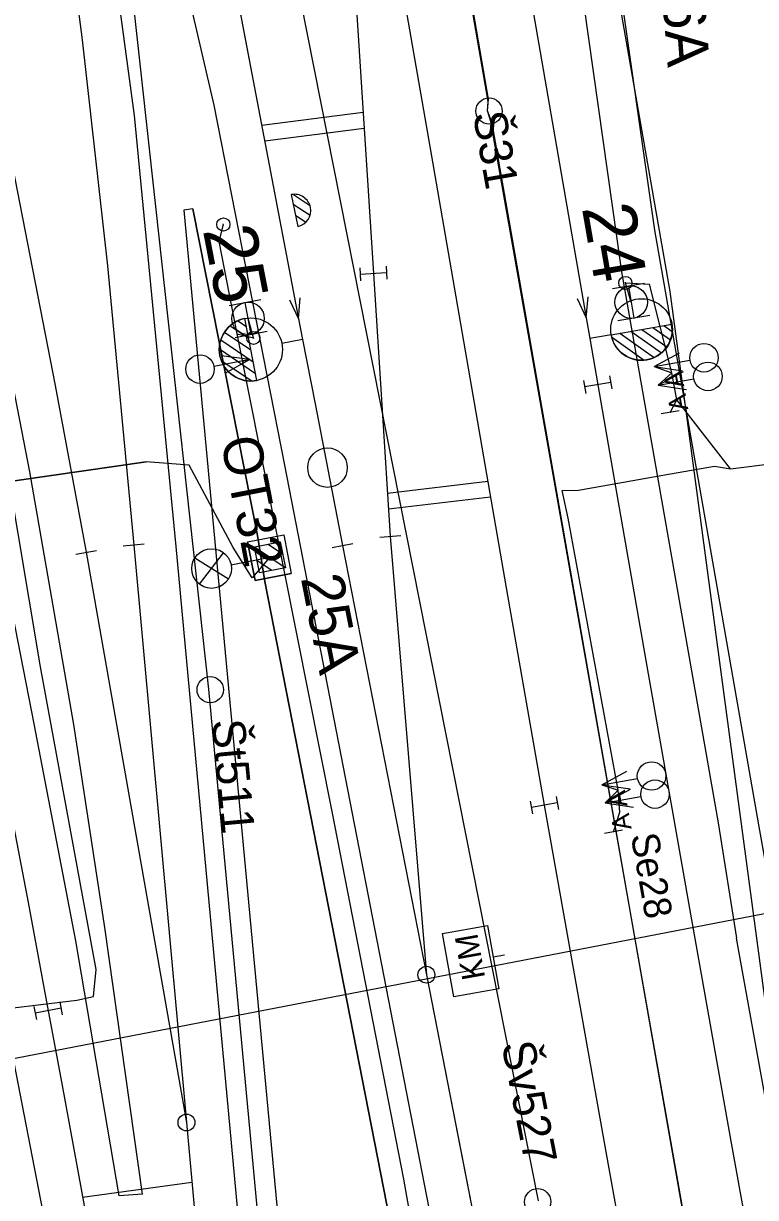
# Model space of a CAD drawing. Extents: x -545736 to -544888, y -1122892 to -1119128.
# Drawn here: x -545134.88 to -545107.08, y -1122251.17 to -1122206.55 of the extents above; entities that cross this region are included whole.
import ezdxf

# ---------------------------------------------------------------- set-up
doc = ezdxf.new("R2010")
doc.units = 0
for name, color, linetype in [('osvětlené plochy-hodnota-obrys', 7, 'Continuous'), ('Vrstva 1 - Koleje', 7, 'Continuous'), ('Vrstva 11 - Trakce', 7, 'Continuous'), ('Vrstva 12 - Trakce zaklady', 7, 'Continuous'), ('Vrstva 19 - Staniceni', 7, 'Continuous'), ('Vrstva 2 - Vyhybky', 7, 'Continuous'), ('Vrstva 25', 7, 'Continuous'), ('Vrstva 26', 7, 'Continuous'), ('Vrstva 27', 7, 'Continuous'), ('Vrstva 28 - zabzar', 7, 'Continuous'), ('Vrstva 3 - Lisy - Pocitaci body', 7, 'Continuous'), ('Vrstva 35', 7, 'Continuous'), ('Vrstva 4 - Teren - stezky - prechody - plochy', 7, 'Continuous'), ('Vrstva 43', 7, 'Continuous'), ('Vrstva 44', 7, 'Continuous'), ('Vrstva 6 - Navesti', 7, 'Continuous'), ('Vrstva 7 - Namezniky-vystroj', 7, 'Continuous')]:
    doc.layers.add(name, color=color, linetype=linetype)

msp = doc.modelspace()

# ---------------------------------------------------------------- linework, layer by layer
at = {"layer": 'osvětlené plochy-hodnota-obrys'}
msp.add_lwpolyline([(-545141.742, -1122267.38), (-545105.592, -1122261.055), (-545104.447, -1122260.603), (-545110.322, -1122216.729), (-545115.194, -1122188.84), (-545124.338, -1122134.271), (-545128.334, -1122064.958), (-545124.139, -1121980.114), (-545129.58, -1121934.549), (-545137.864, -1121889.42)], dxfattribs=at)
at = {"layer": 'Vrstva 1 - Koleje'}
for points in [[(-545150.376, -1122073.507), (-545148.94, -1122081.972), (-545147.487, -1122090.539), (-545146.04, -1122099.073), (-545144.618, -1122107.428), (-545144.249, -1122109.575), (-545143.846, -1122111.921), (-545143.517, -1122113.832), (-545141.973, -1122122.734), (-545140.654, -1122130.261), (-545139.537, -1122136.588), (-545138.129, -1122144.487), (-545136.823, -1122151.755), (-545135.342, -1122159.915), (-545133.505, -1122169.928), (-545132.289, -1122176.511), (-545128.171, -1122198.133), (-545125.192, -1122213.779), (-545124.431, -1122217.772), (-545124.281, -1122218.558)], [(-545148.433, -1122119.752), (-545148.284, -1122120.518), (-545144.456, -1122140.161), (-545138.454, -1122161.395), (-545134.074, -1122176.9), (-545128.171, -1122198.133), (-545124.431, -1122217.772), (-545124.281, -1122218.558)], [(-545148.433, -1122119.752), (-545148.284, -1122120.518), (-545144.456, -1122140.161), (-545140.251, -1122161.74), (-545139.035, -1122167.978), (-545137.307, -1122176.907), (-545135.892, -1122184.869), (-545134.804, -1122191.597), (-545134.686, -1122192.395), (-545133.767, -1122198.628), (-545132.653, -1122207.169), (-545131.692, -1122215.762), (-545130.693, -1122226.379), (-545128.693, -1122248.314), (-545126.878, -1122268.22), (-545126.804, -1122269.027)], [(-545117.326, -1122151.565), (-545117.401, -1122153.261), (-545117.545, -1122156.544), (-545117.734, -1122165.022), (-545117.688, -1122173.358), (-545117.474, -1122180.3), (-545117.213, -1122185.528), (-545116.204, -1122202.146), (-545113.512, -1122217.731), (-545113.376, -1122218.519)], [(-545126.061, -1122172.959), (-545125.928, -1122173.728), (-545125.339, -1122177.139), (-545123.235, -1122189.329), (-545120.41, -1122205.696), (-545119.454, -1122211.219), (-545117.997, -1122219.649), (-545116.548, -1122227.998), (-545115.291, -1122235.168), (-545115.099, -1122236.259), (-545114.375, -1122240.381), (-545112.824, -1122249.082), (-545111.309, -1122257.535), (-545109.035, -1122270.051), (-545107.622, -1122277.751), (-545106.06, -1122286.189), (-545104.406, -1122295.041), (-545103.083, -1122302.064)], [(-545126.061, -1122172.959), (-545125.928, -1122173.728), (-545125.339, -1122177.139), (-545123.235, -1122189.329), (-545122.247, -1122205.823), (-545121.592, -1122216.052), (-545120.953, -1122226.036), (-545119.578, -1122242.701), (-545116.549, -1122258.222), (-545116.396, -1122259.007)], [(-545120.143, -1122179.358), (-545119.035, -1122185.76), (-545116.204, -1122202.146), (-545113.512, -1122217.731), (-545113.376, -1122218.519)], [(-545142.334, -1122200.685), (-545140.419, -1122210.525), (-545138.503, -1122220.353), (-545136.566, -1122230.271), (-545134.71, -1122239.954), (-545133.946, -1122244.067), (-545133.443, -1122246.77), (-545131.615, -1122256.726), (-545129.899, -1122266.071), (-545129.007, -1122270.907), (-545127.892, -1122277.019), (-545124.281, -1122296.703), (-545123.116, -1122309.448)], [(-545137.023, -1122203.118), (-545135.295, -1122211.986), (-545133.676, -1122220.307), (-545132.501, -1122226.646), (-545128.693, -1122248.314), (-545126.878, -1122268.22), (-545126.804, -1122269.027)], [(-545113.376, -1122218.519), (-545113.071, -1122220.278), (-545112.348, -1122224.453), (-545111.157, -1122231.266), (-545109.547, -1122240.396), (-545108.011, -1122249.024), (-545106.448, -1122257.717), (-545104.028, -1122271.035), (-545102.537, -1122279.147), (-545101.024, -1122287.292), (-545099.431, -1122295.796), (-545097.933, -1122303.72), (-545096.244, -1122312.592), (-545094.57, -1122321.295), (-545093.263, -1122328.028), (-545091.542, -1122336.847), (-545089.85, -1122345.509), (-545088.55, -1122352.199), (-545087.631, -1122356.921)], [(-545124.281, -1122218.558), (-545123.805, -1122221.006), (-545122.761, -1122226.391), (-545119.578, -1122242.701), (-545117.206, -1122254.856), (-545116.549, -1122258.222), (-545116.396, -1122259.007)]]:
    msp.add_lwpolyline(points, dxfattribs=at)
at = {"layer": 'Vrstva 11 - Trakce'}
for p, q in [((-545126.107, -1122226.441), (-545124.937, -1122227.228)), ((-545125.586, -1122226.339), (-545125.039, -1122226.708)), ((-545126.009, -1122226.958), (-545125.454, -1122227.332)), ((-545137.244, -1122246.262), (-545105.83, -1122240.196))]:
    msp.add_line(p, q, dxfattribs=at)
msp.add_lwpolyline([(-545125.128, -1122226.249), (-545124.936, -1122227.231), (-545125.918, -1122227.423), (-545126.11, -1122226.441)], close=True, dxfattribs=at)
at = {"layer": 'Vrstva 12 - Trakce zaklady'}
for p, q in [((-545126.37, -1122226.254), (-545124.996, -1122225.986)), ((-545126.083, -1122227.723), (-545124.709, -1122227.455))]:
    msp.add_line(p, q, dxfattribs=at)
for points in [[(-545124.996, -1122225.986), (-545124.709, -1122227.455), (-545126.083, -1122227.723), (-545126.37, -1122226.254), (-545124.996, -1122225.986)], [(-545124.996, -1122225.986), (-545124.996, -1122225.986), (-545124.709, -1122227.455), (-545124.709, -1122227.455)], [(-545126.37, -1122226.254), (-545126.37, -1122226.254), (-545126.083, -1122227.723), (-545126.083, -1122227.723)]]:
    msp.add_lwpolyline(points, dxfattribs=at)
at = {"layer": 'Vrstva 19 - Staniceni'}
msp.add_line((-545116.611, -1122241.96), (-545117.04, -1122242.037), dxfattribs=at)
msp.add_lwpolyline([(-545116.826, -1122243.237), (-545118.537, -1122243.542), (-545118.966, -1122241.138), (-545117.255, -1122240.833)], close=True, dxfattribs=at)
msp.add_circle((-545123.335, -1122223.43), 0.75, dxfattribs=at)
at = {"layer": 'Vrstva 2 - Vyhybky'}
for p, q in [((-545127.032, -1122218.036), (-545126.327, -1122218.513)), ((-545126.74, -1122217.848), (-545126.412, -1122218.07)), ((-545126.017, -1122220.116), (-545126.472, -1122217.759)), ((-545112.565, -1122218.377), (-545110.258, -1122217.979)), ((-545110.976, -1122218.103), (-545110.312, -1122218.571)), ((-545110.557, -1122218.03), (-545110.246, -1122218.25)), ((-545127.245, -1122218.279), (-545126.241, -1122218.958)), ((-545112.566, -1122218.377), (-545113.376, -1122218.519)), ((-545112.565, -1122218.377), (-545112.565, -1122218.377)), ((-545112.544, -1122218.464), (-545111.303, -1122219.34)), ((-545112.23, -1122218.319), (-545110.924, -1122219.24)), ((-545111.812, -1122218.246), (-545110.651, -1122219.066)), ((-545111.394, -1122218.175), (-545110.45, -1122218.841)), ((-545127.442, -1122218.919), (-545126.069, -1122219.846)), ((-545127.384, -1122218.571), (-545126.155, -1122219.403)), ((-545124.281, -1122218.558), (-545125.066, -1122218.71)), ((-545127.368, -1122219.354), (-545126.215, -1122220.134)), ((-545121.352, -1122226.069), (-545120.554, -1122226.003)), ((-545132.894, -1122226.719), (-545132.108, -1122226.573)), ((-545130.295, -1122226.343), (-545131.091, -1122226.415)), ((-545123.154, -1122226.468), (-545122.368, -1122226.314))]:
    msp.add_line(p, q, dxfattribs=at)
for points in [[(-545132.289, -1122176.511), (-545128.171, -1122198.133), (-545124.431, -1122217.772), (-545124.281, -1122218.558)], [(-545119.035, -1122185.76), (-545116.204, -1122202.146), (-545113.512, -1122217.731), (-545113.376, -1122218.519)], [(-545124.779, -1122217.052), (-545124.431, -1122217.772), (-545124.372, -1122216.974)], [(-545113.848, -1122217.005), (-545113.512, -1122217.731), (-545113.439, -1122216.934)], [(-545120.953, -1122226.036), (-545119.578, -1122242.701)], [(-545130.693, -1122226.379), (-545128.693, -1122248.314), (-545126.878, -1122268.22), (-545126.804, -1122269.027)], [(-545122.761, -1122226.391), (-545119.578, -1122242.701), (-545116.549, -1122258.222), (-545116.396, -1122259.007)], [(-545132.501, -1122226.646), (-545128.693, -1122248.314)]]:
    msp.add_lwpolyline(points, dxfattribs=at)
for centre, radius in [((-545111.405, -1122218.178), 1.17), ((-545126.245, -1122218.938), 1.2), ((-545119.578, -1122242.701), 0.32), ((-545128.693, -1122248.314), 0.32)]:
    msp.add_circle(centre, radius, dxfattribs=at)
for centre, radius, start, end in [((-545126.245, -1122218.938), 1.2, 100.9396, 280.9396), ((-545111.411, -1122218.178), 1.171, 189.8205, 9.7813)]:
    msp.add_arc(centre, radius, start, end, dxfattribs=at)
at = {"layer": 'Vrstva 25'}
for p, q in [((-545128.374, -1122226.86), (-545127.091, -1122227.653)), ((-545128.196, -1122227.859), (-545127.281, -1122226.661)), ((-545126.996, -1122227.121), (-545125.523, -1122226.836))]:
    msp.add_line(p, q, dxfattribs=at)
msp.add_circle((-545127.736, -1122227.263), 0.754, dxfattribs=at)
at = {"layer": 'Vrstva 26'}
for points in [[(-545149.701, -1122226.017), (-545130.219, -1122223.203)], [(-545125.523, -1122226.836), (-545126.199, -1122227.617), (-545126.923, -1122226.469), (-545128.585, -1122223.338), (-545130.219, -1122223.203), (-545149.701, -1122226.017), (-545149.372, -1122227.635), (-545145.776, -1122245.312), (-545145.608, -1122246.135)]]:
    msp.add_lwpolyline(points, dxfattribs=at)
at = {"layer": 'Vrstva 27'}
for p, q in [((-545127.285, -1122214.214), (-545127.295, -1122214.166)), ((-545112.024, -1122216.385), (-545112.016, -1122216.435)), ((-545126.155, -1122218.475), (-545126.145, -1122218.525))]:
    msp.add_line(p, q, dxfattribs=at)
for centre in [(-545127.29, -1122214.19), (-545112.02, -1122216.41), (-545126.15, -1122218.5)]:
    msp.add_circle(centre, 0.25, dxfattribs=at)
at = {"layer": 'Vrstva 28 - zabzar'}
for p, q in [((-545126.56, -1122219.38), (-545126.29, -1122219.32)), ((-545110.32, -1122221.33), (-545110.06, -1122220.85))]:
    msp.add_line(p, q, dxfattribs=at)
for points in [[(-545136.66, -1122244.12), (-545132.86, -1122243.67), (-545132.22, -1122243.53), (-545132.12, -1122242.5), (-545134.24, -1122231), (-545136.38, -1122218.29), (-545140.4, -1122198.68), (-545141.27, -1122195.81), (-545142.27, -1122190.49), (-545142.25, -1122189.04)], [(-545116.39, -1122269.41), (-545116.77, -1122268.97), (-545117.15, -1122267.28), (-545117.77, -1122264.76), (-545117.84, -1122264.11), (-545117.97, -1122262.72), (-545118.74, -1122259.08), (-545119.57, -1122255.36), (-545120.44, -1122250.47), (-545123.14, -1122236.56), (-545126.76, -1122218.35), (-545127.45, -1122214.83), (-545127.29, -1122214.19)], [(-545111.8, -1122217.14), (-545112.02, -1122216.41), (-545111.11, -1122216.46)], [(-545108.03, -1122223.48), (-545110.06, -1122220.85), (-545110.26, -1122219.82), (-545111.11, -1122216.46)], [(-545126.76, -1122218.35), (-545126.15, -1122218.5), (-545126.35, -1122217.76)], [(-545110.93, -1122219.58), (-545110.26, -1122219.82), (-545110.78, -1122220.29)], [(-545112.47, -1122237.27), (-545112.23, -1122236.52), (-545112.29, -1122235.69), (-545114.19, -1122225.35), (-545114.42, -1122224.3), (-545113.8, -1122224.28), (-545110.6, -1122223.72), (-545108.64, -1122223.37), (-545108.03, -1122223.48), (-545103.1, -1122222.86), (-545099.31, -1122222.23)], [(-545112.92, -1122235.48), (-545112.29, -1122235.69), (-545112.79, -1122236.17)]]:
    msp.add_lwpolyline(points, dxfattribs=at)
at = {"layer": 'Vrstva 3 - Lisy - Pocitaci body'}
for p, q in [((-545124.71, -1122213.055), (-545124.464, -1122214.262)), ((-545124.627, -1122213.044), (-545124.014, -1122213.451)), ((-545124.638, -1122213.41), (-545123.999, -1122213.833)), ((-545124.551, -1122213.838), (-545124.154, -1122214.096)), ((-545124.464, -1122214.262), (-545124.464, -1122214.262)), ((-545122.107, -1122215.834), (-545122.075, -1122216.333)), ((-545121.109, -1122215.771), (-545121.077, -1122216.27)), ((-545121.093, -1122216.02), (-545122.091, -1122216.084)), ((-545111.298, -1122216.428), (-545112.512, -1122216.638)), ((-545111.905, -1122216.533), (-545111.695, -1122217.747)), ((-545127.073, -1122217.273), (-545125.863, -1122217.037)), ((-545126.232, -1122218.365), (-545126.468, -1122217.155)), ((-545111.088, -1122217.642), (-545112.302, -1122217.852)), ((-545126.837, -1122218.483), (-545125.627, -1122218.247)), ((-545126.29, -1122219.32), (-545127.645, -1122219.584)), ((-545126.29, -1122219.32), (-545127.372, -1122219.179)), ((-545126.29, -1122219.32), (-545127.24, -1122219.856)), ((-545110.93, -1122219.58), (-545109.969, -1122219.064)), ((-545110.93, -1122219.58), (-545109.57, -1122219.345)), ((-545110.93, -1122219.58), (-545109.851, -1122219.744)), ((-545110.78, -1122220.29), (-545109.819, -1122219.774)), ((-545113.606, -1122220.117), (-545113.521, -1122220.61)), ((-545112.578, -1122220.193), (-545113.564, -1122220.363)), ((-545112.621, -1122219.946), (-545112.536, -1122220.439)), ((-545110.78, -1122220.29), (-545109.42, -1122220.055)), ((-545110.78, -1122220.29), (-545109.701, -1122220.454)), ((-545112.92, -1122235.48), (-545111.961, -1122234.961)), ((-545112.92, -1122235.48), (-545111.561, -1122235.241)), ((-545112.92, -1122235.48), (-545111.841, -1122235.64)), ((-545114.65, -1122235.926), (-545114.563, -1122236.419)), ((-545112.79, -1122236.17), (-545111.831, -1122235.651)), ((-545112.79, -1122236.17), (-545111.431, -1122235.93)), ((-545115.635, -1122236.099), (-545115.548, -1122236.592)), ((-545114.607, -1122236.172), (-545115.591, -1122236.346)), ((-545112.79, -1122236.17), (-545111.711, -1122236.33)), ((-545134.483, -1122243.913), (-545134.392, -1122244.404)), ((-545133.454, -1122243.976), (-545134.438, -1122244.158)), ((-545133.5, -1122243.73), (-545133.409, -1122244.221))]:
    msp.add_line(p, q, dxfattribs=at)
for centre, radius in [((-545111.799, -1122217.142), 0.616), ((-545126.351, -1122217.758), 0.616), ((-545109.035, -1122219.254), 0.542), ((-545128.177, -1122219.685), 0.542), ((-545108.885, -1122219.964), 0.542), ((-545111.026, -1122235.148), 0.542), ((-545110.896, -1122235.838), 0.542)]:
    msp.add_circle(centre, radius, dxfattribs=at)
for start, end in [(11.5066, 101.5066), (281.5066, 11.5066)]:
    msp.add_arc((-545124.587, -1122213.658), 0.616, start, end, dxfattribs=at)
at = {"layer": 'Vrstva 35'}
msp.add_lwpolyline([(-545113.8, -1122224.28), (-545110.6, -1122223.72), (-545108.64, -1122223.37)], dxfattribs=at)
at = {"layer": 'Vrstva 4 - Teren - stezky - prechody - plochy'}
for points in [[(-545130.366, -1122251.034), (-545131.253, -1122251.107), (-545132.894, -1122241.41), (-545134.482, -1122233.166), (-545143.993, -1122184.403), (-545152.068, -1122142.857), (-545160.819, -1122097.773), (-545168.806, -1122057.035), (-545170.526, -1122047.801), (-545171.946, -1122039.29), (-545172.394, -1122035.194), (-545171.448, -1122035.061)], [(-545130.366, -1122251.034), (-545131.796, -1122240.905), (-545132.966, -1122233.188), (-545134.639, -1122223.584), (-545142.301, -1122184.068), (-545150.498, -1122141.846), (-545159.147, -1122097.573), (-545167.246, -1122056.111), (-545171.448, -1122035.061)], [(-545107.25, -1122099.027), (-545108.284, -1122098.857), (-545108.463, -1122099.889), (-545109.116, -1122099.726), (-545111.517, -1122114.732), (-545113.636, -1122128.722), (-545114.924, -1122140.407), (-545115.72, -1122150.82), (-545116.074, -1122160.412), (-545116.164, -1122170.31), (-545115.882, -1122181.058), (-545115.315, -1122190.391), (-545114.306, -1122200.841), (-545112.168, -1122215.989), (-545108.495, -1122236.923), (-545107.8, -1122241.308)], [(-545107.25, -1122099.027), (-545109.842, -1122114.686), (-545111.989, -1122128.351), (-545113.399, -1122140.603), (-545114.133, -1122150.894), (-545114.519, -1122160.493), (-545114.536, -1122161.933), (-545114.651, -1122170.109), (-545114.316, -1122181.41), (-545113.904, -1122187.97), (-545113.738, -1122189.62), (-545112.509, -1122202.943), (-545112.353, -1122204.266), (-545110.91, -1122214.403), (-545106.965, -1122237.004), (-545106.526, -1122239.499)], [(-545134.419, -1122184.931), (-545133.462, -1122184.779), (-545130.902, -1122195.623), (-545127.657, -1122209.652), (-545124.969, -1122223.333), (-545117.683, -1122260.831), (-545115.72, -1122271.777), (-545113.985, -1122282.824), (-545112.604, -1122294.484), (-545110.794, -1122311.915), (-545109.689, -1122325.696), (-545109.014, -1122339.852), (-545108.943, -1122350.57), (-545109.184, -1122365.288), (-545109.46, -1122371.016)], [(-545134.419, -1122184.931), (-545132.535, -1122196.254), (-545130.677, -1122210.051), (-545129.096, -1122226.431), (-545125.676, -1122263.286), (-545123.016, -1122292.195), (-545121.493, -1122309.846), (-545120.342, -1122322.797), (-545120.169, -1122324.632), (-545119.157, -1122338.738), (-545118.475, -1122352.352), (-545118.073, -1122366.062)], [(-545128.454, -1122213.597), (-545128.794, -1122213.639), (-545127.617, -1122226.25), (-545124.215, -1122262.597), (-545121.706, -1122290.72), (-545121.657, -1122283.47), (-545120.535, -1122281.441), (-545119.113, -1122280.832), (-545116.955, -1122280.752), (-545116.654, -1122280.486), (-545114.758, -1122295.446), (-545113.38, -1122308.216)], [(-545128.454, -1122213.597), (-545128.794, -1122213.639), (-545127.617, -1122226.25), (-545124.215, -1122262.597), (-545121.706, -1122290.72), (-545119.946, -1122309.868), (-545118.778, -1122322.333), (-545118.56, -1122324.778), (-545117.691, -1122338.703), (-545117.015, -1122352.515), (-545116.676, -1122364.827), (-545116.693, -1122366.257)], [(-545112.296, -1122312.079), (-545114.148, -1122294.183), (-545115.445, -1122282.957), (-545116.987, -1122272.242), (-545119.23, -1122260.9), (-545125.721, -1122227.753), (-545125.995, -1122226.006), (-545128.454, -1122213.597)], [(-545128.454, -1122213.597), (-545125.995, -1122226.006), (-545125.721, -1122227.753), (-545119.23, -1122260.9), (-545116.987, -1122272.242), (-545115.445, -1122282.957), (-545114.148, -1122294.183), (-545112.296, -1122312.079), (-545111.317, -1122324.29), (-545111.178, -1122325.732), (-545110.491, -1122341.064), (-545110.45, -1122353.59), (-545110.479, -1122355.177), (-545110.786, -1122365.47), (-545111.003, -1122371.281)], [(-545121.396, -1122364.457), (-545121.715, -1122349.729), (-545122.506, -1122335.393), (-545123.254, -1122325.065), (-545124.429, -1122313.28), (-545125.788, -1122299.621), (-545128.668, -1122281.429), (-545132.975, -1122257.739), (-545136.355, -1122240.354)], [(-545071.756, -1122430.223), (-545074.076, -1122418.135), (-545081.968, -1122377.565), (-545087.268, -1122350.478), (-545095.305, -1122308.703), (-545101.263, -1122277.511), (-545107.8, -1122241.308)]]:
    msp.add_lwpolyline(points, dxfattribs=at)
at = {"layer": 'Vrstva 43'}
for centre in [(-545117.199, -1122209.877), (-545127.789, -1122231.868), (-545115.352, -1122251.329)]:
    msp.add_circle(centre, 0.5, dxfattribs=at)
at = {"layer": 'Vrstva 44'}
for points in [[(-545100.749, -1122302.024), (-545108.572, -1122258.755), (-545108.679, -1122258.214), (-545108.742, -1122257.838), (-545117.129, -1122210.278), (-545117.262, -1122209.864), (-545117.23, -1122209.512), (-545121.572, -1122184.377), (-545121.632, -1122183.916), (-545121.724, -1122183.534), (-545124.194, -1122170.238), (-545124.353, -1122170.102), (-545124.575, -1122169.952), (-545130.38, -1122170.732), (-545130.684, -1122170.66), (-545130.921, -1122170.43), (-545138.173, -1122128.601), (-545138.227, -1122128.313), (-545138.283, -1122127.929), (-545146.258, -1122081.287), (-545146.29, -1122080.665), (-545145.881, -1122080.467), (-545110.994, -1122075.048)], [(-545087.777, -1122369.733), (-545087.826, -1122369.268), (-545095.531, -1122328.847), (-545095.558, -1122328.641), (-545095.651, -1122328.084), (-545100.679, -1122302.692), (-545100.68, -1122302.502), (-545100.738, -1122301.967), (-545108.648, -1122258.473), (-545108.679, -1122258.214), (-545108.763, -1122257.836), (-545117.081, -1122210.337), (-545117.262, -1122209.864), (-545117.215, -1122209.424), (-545121.519, -1122184.436), (-545121.632, -1122183.916), (-545121.7, -1122183.481), (-545124.149, -1122170.255), (-545124.353, -1122170.102)], [(-545115.321, -1122251.296), (-545125.098, -1122201.892), (-545130.698, -1122170.944), (-545130.684, -1122170.66)], [(-545131.879, -1122195.143), (-545127.852, -1122231.843), (-545124.409, -1122268.781), (-545120.831, -1122305.573), (-545120.773, -1122305.736)]]:
    msp.add_lwpolyline(points, dxfattribs=at)
at = {"layer": 'Vrstva 6 - Navesti'}
for p, q in [((-545109.975, -1122221.27), (-545110.665, -1122221.39)), ((-545112.125, -1122237.209), (-545112.815, -1122237.331))]:
    msp.add_line(p, q, dxfattribs=at)
at = {"layer": 'Vrstva 7 - Namezniky-vystroj'}
for p, q in [((-545125.832, -1122210.413), (-545121.984, -1122209.926)), ((-545125.72, -1122211.004), (-545121.946, -1122210.526)), ((-545121.058, -1122224.4), (-545117.251, -1122223.949)), ((-545121.019, -1122225), (-545117.148, -1122224.541)), ((-545132.638, -1122251.153), (-545128.486, -1122250.584))]:
    msp.add_line(p, q, dxfattribs=at)

# ---------------------------------------------------------------- texts
at = {"layer": 'Vrstva 11 - Trakce'}
for s, rotation, p in [('26A', 274.2412, (-545110.693, -1122204.447)), ('25A', 281.0547, (-545124.35, -1122227.626))]:
    msp.add_text(s, height=1.6, rotation=rotation, dxfattribs=at).set_placement(p)
at = {"layer": 'Vrstva 19 - Staniceni'}
msp.add_text('KM', height=0.8728, rotation=100.1071, dxfattribs=at).set_placement((-545117.342, -1122242.813))
at = {"layer": 'Vrstva 2 - Vyhybky'}
for s, rotation, p in [('24', 279.8009, (-545113.676, -1122213.551)), ('25', 280.9396, (-545128.073, -1122214.398))]:
    msp.add_text(s, height=2, rotation=rotation, dxfattribs=at).set_placement(p)
at = {"layer": 'Vrstva 25'}
msp.add_text('OT32', height=1.5, rotation=280.9719, dxfattribs=at).set_placement((-545127.398, -1122222.367))
at = {"layer": 'Vrstva 43'}
for s, rotation, p in [('Š31', 279.9329, (-545117.815, -1122209.985)), ('Št511', 275.2167, (-545127.729, -1122233.039)), ('Šv527', 281.0323, (-545116.729, -1122245.337))]:
    msp.add_text(s, height=1.25, rotation=rotation, dxfattribs=at).set_placement(p)
at = {"layer": 'Vrstva 6 - Navesti'}
for s, height, rotation, p in [('A A ', 0.7, 99.8769, (-545109.63, -1122221.21)), ('A A ', 0.7, 99.9947, (-545111.781, -1122237.149)), ('Se28', 1.05, 280.0743, (-545111.82, -1122237.403))]:
    msp.add_text(s, height=height, rotation=rotation, dxfattribs=at).set_placement(p)

doc.saveas('drawing.dxf')
